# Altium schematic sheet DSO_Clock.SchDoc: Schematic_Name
size A4; CompanyName: University of Melbourne; Engineer: Your Name Here; DocumentNumber: 1; Revision: 0.1; SheetNumber: 1; SheetTotal: 1; Title_Project: Project_Title; StudentNo: Student No.
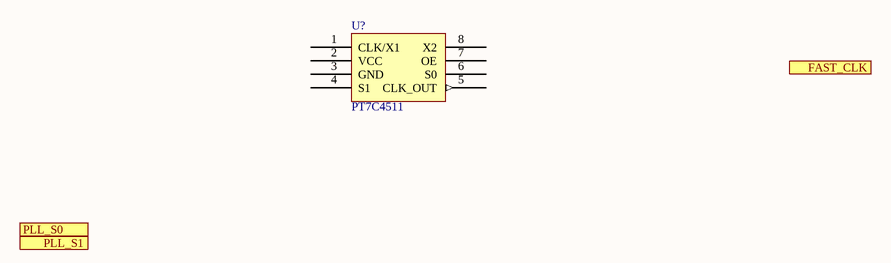
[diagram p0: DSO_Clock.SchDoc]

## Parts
U?  PT7C4511  [SOIC-8]

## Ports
FAST_CLK (out), PLL_S0 (in), PLL_S1 (in)

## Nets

Not connected (* = marked no-connect by the designer): U? 1(CLK/X1) 2(VCC) 3(GND) 4(S1) 5(CLK_OUT) 6(S0) 7(OE) 8(X2)

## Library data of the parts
U? = PT7C4511: PLL Clock Multiplier; Reviewed by: RM - 2018/08/05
